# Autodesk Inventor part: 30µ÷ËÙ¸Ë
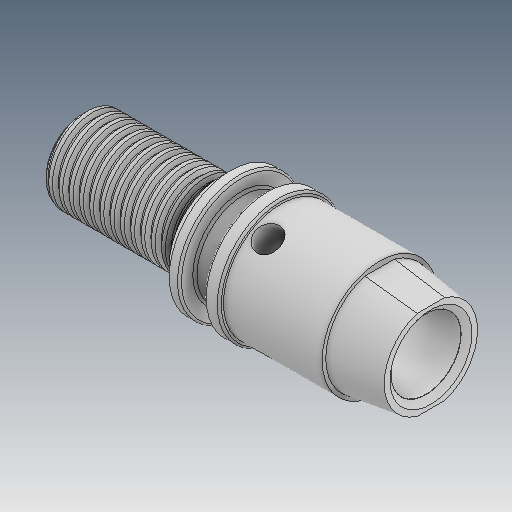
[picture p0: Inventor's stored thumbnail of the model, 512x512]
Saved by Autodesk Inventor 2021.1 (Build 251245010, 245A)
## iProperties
Created: 2019-05
Part Number: 30µ÷ËÙ¸Ë
Material: Ogólny
Document SubType Name: Modeling
Designer: user
Density: 1 g/cm^3
Appearance: Domyślna
Author: user
Revision Number: ÈÎºÎ
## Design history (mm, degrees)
feature "ÊäÈë1"
node "Bryła1"
